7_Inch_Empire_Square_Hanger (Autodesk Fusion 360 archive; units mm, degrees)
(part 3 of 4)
  coincident L95 P256
  coincident L95 P257
  coincident L95 P258
  coincident L95 P259
  coincident L96 P260
  coincident L95 P261
  coincident L95 P262
  coincident L95 P263
  coincident L95 P264
  coincident L96 P265
  coincident L95 P266
  coincident L95 P267
  coincident L95 P268
  coincident L95 P269
  coincident L96 P270
  coincident L95 P271
  coincident L95 P272
  coincident L95 P273
  coincident L95 P274
  coincident L96 P275
  coincident L95 P276
  coincident L95 P277
  coincident L95 P278
  coincident L95 P279
  coincident L96 P280
  coincident L95 P281
  coincident L95 P282
  coincident L95 P283
  coincident P105 L96
  coincident P196 P284
  coincident P289 P290
  coincident P293 P295
  coincident P296 P298
  coincident P197 P295
  coincident P301 P303
  coincident P304 P306
  coincident P309 P311
  coincident P312 P314
  coincident P317 P319
  coincident P320 P322
  coincident P198 P303
  coincident P199 P311
  coincident P200 P319
  coincident P325 P327
  coincident P328 P330
  coincident P333 P335
  coincident P336 P338
  coincident P341 P343
  coincident P344 P346
  coincident P349 P351
  coincident P352 P354
  coincident P357 P359
  coincident P360 P362
  coincident P201 P327
  coincident P202 P335
  coincident P203 P343
  coincident P204 P351
  coincident P205 P359
  coincident P364 P368
  coincident P369 P371
  coincident P363 P368
  coincident P373 P377
  coincident P378 P380
  coincident P372 P377
  coincident P382 P386
  coincident P387 P389
  coincident P381 P386
  coincident P391 P395
  coincident P396 P398
  coincident P390 P395
  coincident P400 P404
  coincident P405 P407
  coincident P399 P404
  coincident P206 P368
  coincident P207 P377
  coincident P208 P386
  coincident P209 P395
  coincident P210 P404
  coincident P410 P411
  coincident P413 P417
  coincident P408 P411
  coincident P411 P416
  coincident P420 P421
  coincident P423 P437
  coincident P418 P421
  coincident P421 P426
  coincident P428 P432
  coincident P433 P435
  coincident P428 P431
  coincident P428 P436
  coincident P439 P443
  coincident P444 P446
  coincident P439 P442
  coincident P439 P447
  coincident P449 P453
  coincident P454 P456
  coincident P449 P452
  coincident P449 P457
  coincident P460 P461
  coincident P463 P467
  coincident P458 P461
  coincident P461 P466
  coincident P470 P471
  coincident P473 P477
  coincident P468 P471
  coincident P471 P476
  coincident P480 P481
  coincident P483 P497
  coincident P478 P481
  coincident P481 P486
  coincident P488 P492
  coincident P493 P495
  coincident P488 P491
  coincident P488 P496
  coincident P500 P501
  coincident P503 P517
  coincident P498 P501
  coincident P501 P506
  coincident P508 P512
  coincident P513 P515
  coincident P508 P511
  coincident P508 P516
  coincident P520 P521
  coincident P523 P537
  coincident P518 P521
  coincident P521 P526
  coincident P528 P532
  coincident P533 P535
  coincident P528 P531
  coincident P528 P536
  coincident P540 P541
  coincident P543 P557
  coincident P538 P541
  coincident P541 P546
  coincident P548 P552
  coincident P553 P555
  coincident P548 P551
  coincident P548 P556
  coincident P560 P561
  coincident P563 P577
  coincident P558 P561
  coincident P561 P566
  coincident P568 P572
  coincident P573 P575
  coincident P568 P571
  coincident P568 P576
  coincident P580 P581
  coincident P583 P587
  coincident P578 P581
  coincident P581 P586
  coincident P590 P591
  coincident P593 P607
  coincident P588 P591
  coincident P591 P596
  coincident P598 P602
  coincident P603 P605
  coincident P598 P601
  coincident P598 P606
  coincident P610 P611
  coincident P613 P627
  coincident P608 P611
  coincident P611 P616
  coincident P618 P622
  coincident P623 P625
  coincident P618 P621
  coincident P618 P626
  coincident P630 P631
  coincident P633 P647
  coincident P628 P631
  coincident P631 P636
  coincident P638 P642
  coincident P643 P645
  coincident P638 P641
  coincident P638 P646
  coincident P650 P651
  coincident P653 P667
  coincident P648 P651
  coincident P651 P656
  coincident P658 P662
  coincident P663 P665
  coincident P658 P661
  coincident P658 P666
  coincident P670 P671
  coincident P673 P687
  coincident P668 P671
  coincident P671 P676
  coincident P678 P682
  coincident P683 P685
  coincident P678 P681
  coincident P678 P686
  coincident P690 P691
  coincident P693 P707
  coincident P688 P691
  coincident P691 P696
  coincident P698 P702
  coincident P703 P705
  coincident P698 P701
  coincident P698 P706
  coincident P710 P711
  coincident P713 P727
  coincident P708 P711
  coincident P711 P716
  coincident P718 P722
  coincident P723 P725
  coincident P718 P721
  coincident P718 P726
  coincident P730 P731
  coincident P733 P747
  coincident P728 P731
  coincident P731 P736
  coincident P738 P742
  coincident P743 P745
  coincident P738 P741
  coincident P738 P746
  coincident P750 P751
  coincident P753 P767
  coincident P748 P751
  coincident P751 P756
  coincident P758 P762
  coincident P763 P765
  coincident P758 P761
  coincident P758 P766
  coincident P211 P421
  coincident P212 P439
  coincident P213 P449
  coincident P214 P461
  coincident P216 P481
  coincident P217 P501
  coincident P221 P581
  coincident P215 P471
  coincident P218 P528
  coincident P219 P541
  coincident P222 P591
  coincident P223 P618
  coincident P224 P631
  coincident P226 P678
  coincident P227 P691
  coincident P228 P711
  coincident P229 P738
  coincident P231 P411
  coincident P220 P561
  coincident P225 P658
  coincident P230 P751
  coincident P232 P428
  coincident P233 P758
  coincident P234 P731
  coincident P235 P718
  coincident P236 P698
  coincident P237 P671
  coincident P238 P651
  coincident P240 P638
  coincident P241 P611
  coincident P239 P598
  coincident P242 P568
  coincident P243 P548
  coincident P244 P521
  coincident P246 P488
  coincident P771 P774
  coincident P775 P777
  coincident P771 P773
  coincident P769 P771
  coincident P771 P778
  coincident P247 P771
  coincident P782 P785
  coincident P786 P788
  coincident P782 P784
  coincident P780 P782
  coincident P782 P789
  coincident P248 P782
  coincident P793 P796
  coincident P797 P799
  coincident P793 P795
  coincident P791 P793
  coincident P793 P800
  coincident P249 P793
  coincident P245 P508
  coincident P804 P807
  coincident P808 P810
  coincident P804 P806
  coincident P802 P804
  coincident P804 P811
  coincident P250 P804
  coincident P815 P818
  coincident P819 P821
  coincident P815 P817
  coincident P813 P815
  coincident P815 P822
  coincident P826 P829
  coincident P830 P832
  coincident P826 P828
  coincident P824 P826
  coincident P826 P833
  coincident P837 P840
  coincident P841 P843
  coincident P837 P839
  coincident P835 P837
  coincident P837 P844
  coincident P848 P851
  coincident P852 P854
  coincident P848 P850
  coincident P846 P848
  coincident P848 P855
  coincident P859 P862
  coincident P863 P865
  coincident P859 P861
  coincident P857 P859
  coincident P859 P866
  coincident P251 P815
  coincident P252 P826
  coincident P253 P837
  coincident P254 P848
  coincident P255 P859
  coincident P875 P877
  coincident P868 P869
  coincident P875 P876
  coincident P874 P875
  coincident P875 P878
  coincident P867 P875
  coincident P887 P889
  coincident P880 P881
  coincident P887 P888
  coincident P886 P887
  coincident P887 P890
  coincident P879 P887
  coincident P899 P901
  coincident P892 P893
  coincident P899 P900
  coincident P898 P899
  coincident P899 P902
  coincident P891 P899
  coincident P911 P913
  coincident P904 P905
  coincident P911 P912
  coincident P910 P911
  coincident P911 P914
  coincident P903 P911
  coincident P923 P925
  coincident P916 P917
  coincident P923 P924
  coincident P922 P923
  coincident P923 P926
  coincident P915 P923
  coincident P935 P937
  coincident P928 P929
  coincident P935 P936
  coincident P934 P935
  coincident P935 P938
  coincident P927 P935
  coincident P947 P949
  coincident P940 P941
  coincident P947 P948
  coincident P946 P947
  coincident P947 P950
  coincident P939 P947
  coincident P959 P961
  coincident P952 P953
  coincident P959 P960
  coincident P958 P959
  coincident P959 P962
  coincident P951 P959
  coincident P971 P973
  coincident P964 P965
  coincident P971 P972
  coincident P970 P971
  coincident P971 P974
  coincident P963 P971
  coincident P256 P875
  coincident P257 P887
  coincident P258 P899
  coincident P259 P911
  coincident P260 P923
  coincident P261 P935
  coincident P262 P947
  coincident P263 P959
  coincident P264 P971
  coincident P977 P979
  coincident P980 P982
  coincident P265 P979
  coincident P983 P985
  coincident P987 P990
  coincident P266 P985
  coincident P991 P993
  coincident P995 P998
  coincident P267 P993
  coincident P999 P1001
  coincident P1003 P1006
  coincident P268 P1001
  coincident P1007 P1009
  coincident P1011 P1014
  coincident P269 P1009
  coincident P1015 P1017
  coincident P1019 P1022
  coincident P270 P1017
  coincident P1023 P1025
  coincident P1027 P1030
  coincident P1031 P1033
  coincident P1035 P1038
  coincident P1039 P1041
  coincident P1043 P1046
  coincident P1047 P1049
  coincident P1051 P1054
  coincident P1055 P1057
  coincident P1059 P1062
  coincident P1063 P1065
  coincident P1067 P1070
  coincident P1071 P1073
  coincident P1075 P1078
  coincident P1079 P1081
  coincident P1083 P1086
  coincident P1087 P1089
  coincident P1091 P1094
  coincident P1095 P1097
  coincident P1099 P1102
  coincident P1103 P1105
  coincident P1107 P1110
  coincident P1111 P1113
  coincident P1115 P1118
  coincident P1119 P1121
  coincident P1123 P1126
  coincident P271 P1025
  coincident P272 P1033
  coincident P273 P1041
  coincident P274 P1049
  coincident P275 P1057
  coincident P276 P1065
  coincident P277 P1073
  coincident P278 P1081
  coincident P279 P1089
  coincident P280 P1097
  coincident P281 P1105
  coincident P282 P1113
  coincident P283 P1121
  dimension "d288" = 2.54
  dimension "d289" = 5.08
  dimension "d540" diameter = 0.635
  dimension "d544" distance P15 P289 = 0.635
  dimension "d545" diameter = 0.635
  dimension "d546" distance P110 P296 = 0.635
  dimension "d547" diameter = 0.635
  dimension "d548" distance P111 P304 = 0.635
  dimension "d549" diameter = 0.635
  dimension "d550" distance P112 P312 = 0.635
  dimension "d551" diameter = 0.635
  dimension "d552" distance P113 P320 = 0.635
  dimension "d553" diameter = 0.635
  dimension "d554" distance P114 P328 = 0.635
  dimension "d555" diameter = 0.635
  dimension "d556" distance P115 P336 = 0.635
  dimension "d557" diameter = 0.635
  dimension "d558" distance P116 P344 = 0.635
  dimension "d559" diameter = 0.635
  dimension "d560" distance P117 P352 = 0.635
  dimension "d561" diameter = 0.635
  dimension "d562" distance P118 P360 = 0.635
  dimension "d563" diameter = 0.635
  dimension "d564" distance P119 P369 = 0.635
  dimension "d565" diameter = 0.635
  dimension "d566" distance P120 P378 = 0.635
  dimension "d567" diameter = 0.635
  dimension "d568" distance P121 P387 = 0.635
  dimension "d569" diameter = 0.635
  dimension "d570" distance P122 P396 = 0.635
  dimension "d571" diameter = 0.635
  dimension "d572" distance P123 P405 = 0.635
  dimension "d573" diameter = 0.635
  dimension "d574" distance P144 P413 = 0.635
  dimension "d575" diameter = 0.635
  dimension "d576" distance P124 P423 = 0.635
  dimension "d577" diameter = 0.635
  dimension "d578" distance P145 P433 = 0.635
  dimension "d581" diameter = 0.635
  dimension "d582" distance P125 P444 = 0.635
  dimension "d585" diameter = 0.635
  dimension "d586" distance P126 P454 = 0.635
  dimension "d587" diameter = 0.635
  dimension "d588" distance P127 P463 = 0.635
  dimension "d591" diameter = 0.635
  dimension "d592" distance P128 P473 = 0.635
  dimension "d595" diameter = 0.635
  dimension "d596" distance P129 P483 = 0.635
  dimension "d597" diameter = 0.635
  dimension "d598" distance P159 P493 = 0.635
  dimension "d599" diameter = 0.635
  dimension "d600" distance P130 P503 = 0.635
  dimension "d601" diameter = 0.635
  dimension "d602" distance P158 P513 = 0.635
  dimension "d603" diameter = 0.635
  dimension "d604" distance P157 P523 = 0.635
  dimension "d605" diameter = 0.635
  dimension "d606" distance P131 P533 = 0.635
  dimension "d607" diameter = 0.635
  dimension "d608" distance P132 P543 = 0.635
  dimension "d609" diameter = 0.635
  dimension "d610" distance P156 P553 = 0.635
  dimension "d611" diameter = 0.635
  dimension "d612" distance P133 P563 = 0.635
  dimension "d613" diameter = 0.635
  dimension "d614" distance P155 P573 = 0.635
  dimension "d615" diameter = 0.635
  dimension "d616" distance P136 P583 = 0.635
  dimension "d619" diameter = 0.635
  dimension "d620" distance P134 P593 = 0.635
  dimension "d621" diameter = 0.635
  dimension "d622" distance P152 P603 = 0.635
  dimension "d623" diameter = 0.635
  dimension "d624" distance P154 P613 = 0.635
  dimension "d625" diameter = 0.635
  dimension "d626" distance P135 P623 = 0.635
  dimension "d627" diameter = 0.635
  dimension "d628" distance P137 P633 = 0.635
  dimension "d629" diameter = 0.635
  dimension "d630" distance P153 P643 = 0.635
  dimension "d631" diameter = 0.635
  dimension "d632" distance P151 P653 = 0.635
  dimension "d633" diameter = 0.635
  dimension "d634" distance P138 P663 = 0.635
  dimension "d635" diameter = 0.635
  dimension "d636" distance P150 P673 = 0.635
  dimension "d637" diameter = 0.635
  dimension "d638" distance P139 P683 = 0.635
  dimension "d639" diameter = 0.635
  dimension "d640" distance P140 P693 = 0.635
  dimension "d641" diameter = 0.635
  dimension "d642" distance P149 P703 = 0.635
  dimension "d643" diameter = 0.635
  dimension "d644" distance P141 P713 = 0.635
  dimension "d645" diameter = 0.635
  dimension "d646" distance P148 P723 = 0.635
  dimension "d647" diameter = 0.635
  dimension "d648" distance P146 P733 = 0.635
  dimension "d649" diameter = 0.635
  dimension "d650" distance P142 P743 = 0.635
  dimension "d651" diameter = 0.635
  dimension "d652" distance P143 P753 = 0.635
  dimension "d653" diameter = 0.635
  dimension "d654" distance P147 P763 = 0.635
  dimension "d655" diameter = 0.635
  dimension "d656" distance P160 P777 = 0.635
  dimension "d657" diameter = 0.635
  dimension "d658" distance P161 P788 = 0.635
  dimension "d659" diameter = 0.635
  dimension "d660" distance P162 P799 = 0.635
  dimension "d661" diameter = 0.635
  dimension "d662" distance P195 P810 = 0.635
  dimension "d663" diameter = 0.635
  dimension "d664" distance P163 P821 = 0.635
  dimension "d665" diameter = 0.635
  dimension "d666" distance P164 P832 = 0.635
  dimension "d667" diameter = 0.635
  dimension "d668" distance P165 P843 = 0.635
  dimension "d669" diameter = 0.635
  dimension "d670" distance P166 P854 = 0.635
  dimension "d671" diameter = 0.635
  dimension "d673" diameter = 0.635
  dimension "d675" diameter = 0.635
  dimension "d677" diameter = 0.635
  dimension "d679" diameter = 0.635
  dimension "d681" diameter = 0.635
  dimension "d683" diameter = 0.635
  dimension "d685" diameter = 0.635
  dimension "d687" diameter = 0.635
  dimension "d689" diameter = 0.635
  dimension "d693" distance P167 P865 = 0.635
  dimension "d694" distance P168 P868 = 0.635
  dimension "d695" distance P169 P880 = 0.635
  dimension "d696" distance P170 P892 = 0.635
  dimension "d697" distance P171 P904 = 0.635
  dimension "d698" distance P173 P916 = 0.635
  dimension "d699" distance P172 P928 = 0.635
  dimension "d700" distance P174 P940 = 0.635
  dimension "d701" distance P175 P952 = 0.635
  dimension "d702" distance P176 P964 = 0.635
  dimension "d703" diameter = 0.635
  dimension "d705" distance P177 P980 = 0.635
  dimension "d709" diameter = 0.635
  dimension "d710" distance P178 P987 = 0.635
  dimension "d711" diameter = 0.635
  dimension "d712" distance P179 P995 = 0.635
  dimension "d713" diameter = 0.635
  dimension "d714" distance P180 P1003 = 0.635
  dimension "d715" diameter = 0.635
  dimension "d716" distance P181 P1011 = 0.635
  dimension "d717" diameter = 0.635
  dimension "d718" distance P182 P1019 = 0.635
  dimension "d719" diameter = 0.635
  dimension "d720" distance P183 P1027 = 0.635
  dimension "d721" diameter = 0.635
  dimension "d722" distance P184 P1035 = 0.635
  dimension "d723" diameter = 0.635
  dimension "d724" distance P185 P1043 = 0.635
  dimension "d725" diameter = 0.635
  dimension "d726" distance P186 P1051 = 0.635
  dimension "d727" diameter = 0.635
  dimension "d728" distance P187 P1059 = 0.635
  dimension "d729" diameter = 0.635
  dimension "d730" distance P188 P1067 = 0.635
  dimension "d731" diameter = 0.635
  dimension "d732" distance P189 P1075 = 0.635
  dimension "d733" diameter = 0.635
  dimension "d734" distance P190 P1083 = 0.635
  dimension "d735" diameter = 0.635
  dimension "d736" distance P191 P1091 = 0.635
  dimension "d737" diameter = 0.635
  dimension "d738" distance P192 P1099 = 0.635
  dimension "d739" diameter = 0.635
  dimension "d740" distance P193 P1107 = 0.635
  dimension "d741" diameter = 0.635
  dimension "d742" distance P194 P1115 = 0.635
  dimension "d743" diameter = 0.635
  dimension "d744" distance P103 P1123 = 0.635
  dimension "d751" distance P1123 P1129 = 1.905
sketch "Front_Angular_Scale_Text" plane through (0, 0, 0) normal (0, 1, 0) x axis (1, 0, 0)
  line L1 (176.2125, 0) -> (0, 0)
  line L2 (0, 1.5875) -> (0, -176.2125)
  line L3 (0, -176.2125) -> (177.8, 1.5875)
  line L4 (-3.5921, -172.6204) -> (174.2079, 5.1796)
  line L5 (155.2888, -13.7395) -> (161.8891, -14.3234)
  line L6 (143.4449, -25.5834) -> (149.5418, -26.6707)
  line L7 (132.9775, -36.0508) -> (138.6294, -37.5831)
  line L8 (123.5209, -45.5074) -> (128.7709, -47.4416)
  line L9 (114.8064, -54.2219) -> (119.686, -56.5265)
  line L10 (106.6276, -62.4007) -> (111.1596, -65.0529)
  line L11 (98.8189, -70.2094) -> (103.019, -73.1935)
  line L12 (91.2406, -77.7877) -> (95.1186, -81.0939)
  line L13 (83.7683, -85.26) -> (87.3287, -88.8838)
  line L14 (76.2844, -92.7439) -> (79.5267, -96.6858)
  line L15 (68.6703, -100.358) -> (71.589, -104.6235)
  line L16 (60.7994, -108.2289) -> (63.3836, -112.8289)
  line L17 (52.5278, -116.5005) -> (54.7604, -121.4521)
  line L18 (43.6829, -125.3453) -> (45.5396, -130.6729)
  line L19 (34.0482, -134.9801) -> (35.4954, -140.7171)
  line L20 (23.3386, -145.6897) -> (24.3306, -151.8819)
  line L21 (11.1634, -157.8649) -> (11.6379, -164.5746)
  line L22 (151.9887, -13.4475) -> (155.2888, -13.7395)
  line L23 (140.3965, -25.0397) -> (143.4449, -25.5834)
  line L24 (130.1515, -35.2847) -> (132.9775, -36.0508)
  line L25 (120.8959, -44.5403) -> (123.5209, -45.5074)
  line L26 (112.3666, -53.0696) -> (114.8064, -54.2219)
  line L27 (104.3616, -61.0746) -> (106.6276, -62.4007)
  line L28 (96.7188, -68.7174) -> (98.8189, -70.2094)
  line L29 (89.3016, -76.1346) -> (91.2406, -77.7877)
  line L30 (81.9881, -83.4481) -> (83.7683, -85.26)
  line L31 (74.6632, -90.773) -> (76.2844, -92.7439)
  line L32 (67.211, -98.2252) -> (68.6703, -100.358)
  line L33 (59.5073, -105.9289) -> (60.7994, -108.2289)
  line L34 (51.4115, -114.0247) -> (52.5278, -116.5005)
  line L35 (42.7546, -122.6816) -> (43.6829, -125.3453)
  line L36 (33.3246, -132.1116) -> (34.0482, -134.9801)
  line L37 (22.8427, -142.5935) -> (23.3386, -145.6897)
  line L38 (10.9262, -154.51) -> (11.1634, -157.8649)
  line L39 (11.5708, -153.8654) -> (10.2816, -155.1546)
  line L40 (23.3041, -142.1321) -> (22.3812, -143.0549)
  line L41 (33.8532, -131.5829) -> (32.796, -132.6402)
  line L42 (43.7412, -121.695) -> (41.768, -123.6682)
  line L43 (52.5351, -112.9011) -> (50.2878, -115.1484)
  line L44 (60.7398, -104.6964) -> (58.2748, -107.1613)
  line L45 (69.0885, -96.3477) -> (65.3334, -100.1028)
  line L46 (76.888, -88.5482) -> (72.4384, -92.9978)
  line L47 (84.2675, -81.1687) -> (79.7087, -85.7275)
  line L48 (91.8124, -73.6238) -> (86.7908, -78.6454)
  line L49 (98.2574, -67.1788) -> (95.1802, -70.256)
  line L50 (106.2156, -59.2205) -> (102.5075, -62.9287)
  line L51 (113.766, -51.6702) -> (110.9671, -54.469)
  line L52 (122.4821, -42.9541) -> (119.3098, -46.1264)
  line L53 (132.1083, -33.3279) -> (128.1947, -37.2415)
  line L54 (142.7391, -22.6971) -> (138.0539, -27.3823)
  line L55 (154.2497, -11.1865) -> (149.7278, -15.7084)
  point P11 (155.2888, -13.7395)
  point P44 (155.2888, -13.7395)
  point P13 (143.4449, -25.5834)
  point P46 (143.4449, -25.5834)
  point P15 (132.9775, -36.0508)
  point P48 (132.9775, -36.0508)
  point P17 (123.5209, -45.5074)
  point P50 (123.5209, -45.5074)
  point P19 (114.8064, -54.2219)
  point P52 (114.8064, -54.2219)
  point P21 (106.6276, -62.4007)
  point P54 (106.6276, -62.4007)
  point P23 (98.8189, -70.2094)
  point P56 (98.8189, -70.2094)
  point P25 (91.2406, -77.7877)
  point P58 (91.2406, -77.7877)
  point P27 (83.7683, -85.26)
  point P60 (83.7683, -85.26)
  point P29 (76.2844, -92.7439)
  point P62 (76.2844, -92.7439)
  point P31 (68.6703, -100.358)
  point P64 (68.6703, -100.358)
  point P33 (60.7994, -108.2289)
  point P66 (60.7994, -108.2289)
  point P35 (52.5278, -116.5005)
  point P68 (52.5278, -116.5005)
  point P37 (43.6829, -125.3453)
  point P70 (43.6829, -125.3453)
  point P39 (34.0482, -134.9801)
  point P72 (34.0482, -134.9801)
  point P41 (23.3386, -145.6897)
  point P74 (23.3386, -145.6897)
  point P43 (11.1634, -157.8649)
  point P76 (11.1634, -157.8649)
  point P77 (10.9262, -154.51)
  point P75 (22.8427, -142.5935)
  point P45 (151.9887, -13.4475)
  point P47 (140.3965, -25.0397)
  point P49 (130.1515, -35.2847)
  point P51 (120.8959, -44.5403)
  point P53 (112.3666, -53.0696)
  point P55 (104.3616, -61.0746)
  point P57 (96.7188, -68.7174)
  point P59 (89.3016, -76.1346)
  point P61 (81.9881, -83.4481)
  point P63 (74.6632, -90.773)
  point P65 (67.211, -98.2252)
  point P67 (59.5073, -105.9289)
  point P69 (51.4115, -114.0247)
  point P71 (42.7546, -122.6816)
  point P73 (33.3246, -132.1116)
  coincident P11 P44
  parallel L5 L22
  coincident P13 P46
  parallel L6 L23
  coincident P15 P48
  parallel L7 L24
  coincident P17 P50
  parallel L8 L25
  coincident P19 P52
  parallel L9 L26
  coincident P21 P54
  parallel L10 L27
  coincident P23 P56
  parallel L11 L28
  coincident P25 P58
  parallel L12 L29
  coincident P27 P60
  coincident P29 P62
  parallel L14 L31
  coincident P31 P64
  parallel L15 L32
  coincident P33 P66
  parallel L16 L33
  coincident P35 P68
  parallel L17 L34
  coincident P37 P70
  parallel L18 L35
  coincident P39 P72
  parallel L19 L36
  coincident P41 P74
  parallel L20 L37
  coincident P43 P76
  parallel L21 L38
  midpoint P77 L39
  parallel L4 L39
  midpoint P75 L40
  parallel L4 L40
  midpoint P45 L55
  midpoint P47 L54
  midpoint P49 L53
  midpoint P51 L52
  midpoint P53 L51
  midpoint P55 L50
  midpoint P57 L49
  midpoint P59 L48
  midpoint P61 L47
  midpoint P63 L46
  midpoint P65 L45
  midpoint P67 L44
  midpoint P69 L43
  midpoint P71 L42
  midpoint P73 L41
  collinear L39 L40
  collinear L40 L41
  collinear L41 L42
  collinear L42 L43
  collinear L43 L44
  collinear L44 L45
  collinear L45 L46
  collinear L46 L47
  collinear L47 L48
  parallel L13 L30
  collinear L48 L49
  collinear L49 L50
  collinear L50 L51
  collinear L51 L52
  collinear L52 L53
  collinear L53 L54
  collinear L54 L55
  dimension "d929" distance L4 L55 = 2.54
  dimension "d930" Text1-Height = 3.175
  dimension "d931" Text2-Height = 3.175
  dimension "d932" Text3-Height = 3.175
  dimension "d933" Text4-Height = 3.175
  dimension "d934" Text5-Height = 3.175
  dimension "d935" Text6-Height = 3.175
  dimension "d936" Text7-Height = 3.175
  dimension "d937" Text8-Height = 3.175
  dimension "d938" Text9-Height = 3.175
sketch "Back_Angular_Text" plane through (0, 0, 0) normal (0, 1, 0) x axis (1, 0, 0)
  line L1 (89.3016, -76.1346) -> (91.2406, -77.7877)
  line L2 (23.304, -142.1321) -> (22.3813, -143.0549)
  line L3 (91.8124, -73.6238) -> (86.7908, -78.6454)
  line L4 (10.9262, -154.51) -> (11.1634, -157.8649)
  line L5 (52.5278, -116.5005) -> (54.7604, -121.4521)
  line L6 (33.8532, -131.583) -> (32.796, -132.6402)
  line L7 (11.5708, -153.8654) -> (10.2816, -155.1546)
  line L8 (34.0482, -134.9801) -> (35.4954, -140.7171)
  line L9 (42.7546, -122.6816) -> (43.6829, -125.3453)
  line L10 (22.8427, -142.5935) -> (23.3386, -145.6897)
  line L11 (33.3246, -132.1116) -> (34.0482, -134.9801)
  line L12 (11.1634, -157.8649) -> (11.6379, -164.5746)
  line L13 (106.2156, -59.2206) -> (102.5075, -62.9286)
  line L14 (76.8879, -88.5483) -> (72.4385, -92.9977)
  line L15 (98.8189, -70.2094) -> (103.019, -73.1935)
  line L16 (96.7188, -68.7174) -> (98.8189, -70.2094)
  line L17 (81.9881, -83.4481) -> (83.7683, -85.26)
  line L18 (112.3666, -53.0696) -> (114.8064, -54.2219)
  line L19 (132.1083, -33.3279) -> (128.1948, -37.2414)
  line L20 (120.8959, -44.5403) -> (123.5209, -45.5074)
  line L21 (155.2888, -13.7395) -> (161.8891, -14.3234)
  line L22 (104.3616, -61.0746) -> (106.6276, -62.4007)
  line L23 (123.5209, -45.5074) -> (128.7709, -47.4416)
  line L24 (60.7994, -108.2289) -> (63.3836, -112.8289)
  line L25 (91.2406, -77.7877) -> (95.1186, -81.0939)
  line L26 (83.7683, -85.26) -> (87.3287, -88.8838)
  line L27 (60.7398, -104.6964) -> (58.2749, -107.1613)
  line L28 (106.6276, -62.4007) -> (111.1596, -65.0529)
  line L29 (114.8064, -54.2219) -> (119.686, -56.5265)
  line L30 (113.766, -51.6702) -> (110.9672, -54.469)
  line L31 (84.2674, -81.1687) -> (79.7088, -85.7274)
  line L32 (122.4821, -42.9541) -> (119.3098, -46.1264)
  line L33 (43.7412, -121.695) -> (41.768, -123.6682)
  line L34 (142.7391, -22.6971) -> (138.054, -27.3822)
  line L35 (98.2574, -67.1788) -> (95.1802, -70.2559)
  line L36 (51.4115, -114.0247) -> (52.5278, -116.5005)
  line L37 (68.6703, -100.358) -> (71.589, -104.6235)
  line L38 (23.3386, -145.6897) -> (24.3306, -151.8819)
  line L39 (43.6829, -125.3453) -> (45.5396, -130.6729)
  line L40 (76.2844, -92.7439) -> (79.5267, -96.6858)
  line L41 (143.4449, -25.5834) -> (149.5418, -26.6707)
  line L42 (59.5073, -105.9289) -> (60.7994, -108.2289)
  line L43 (130.1515, -35.2847) -> (132.9775, -36.0508)
  line L44 (67.211, -98.2252) -> (68.6703, -100.358)
  line L45 (132.9775, -36.0508) -> (138.6294, -37.5831)
  line L46 (74.6632, -90.773) -> (76.2844, -92.7439)
  line L47 (154.2496, -11.1866) -> (149.7278, -15.7084)
  line L48 (151.9887, -13.4475) -> (155.2888, -13.7395)
  line L49 (140.3965, -25.0397) -> (143.4449, -25.5834)
  line L50 (52.5351, -112.9011) -> (50.2878, -115.1484)
  line L51 (69.0885, -96.3477) -> (65.3335, -100.1027)
  line L52 (0, -176.2125) -> (177.8, 1.5875)
  line L53 (-3.5921, -172.6204) -> (174.2079, 5.1796)
  line L54 (176.2125, 0) -> (0, 0)
  line L55 (0, 1.5875) -> (0, -176.2125)
  point P16 (155.2888, -13.7395)
  point P72 (155.2888, -13.7395)
  point P27 (143.4449, -25.5834)
  point P98 (143.4449, -25.5834)
  point P24 (132.9775, -36.0508)
  point P100 (132.9775, -36.0508)
  point P28 (123.5209, -45.5074)
  point P53 (123.5209, -45.5074)
  point P17 (114.8064, -54.2219)
  point P83 (114.8064, -54.2219)
  point P18 (106.6276, -62.4007)
  point P85 (106.6276, -62.4007)
  point P11 (98.8189, -70.2094)
  point P19 (98.8189, -70.2094)
  point P20 (91.2406, -77.7877)
  point P80 (91.2406, -77.7877)
  point P14 (83.7683, -85.26)
  point P34 (83.7683, -85.26)
  point P22 (76.2844, -92.7439)
  point P71 (76.2844, -92.7439)
  point P37 (68.6703, -100.358)
  point P62 (68.6703, -100.358)
  point P39 (60.7994, -108.2289)
  point P60 (60.7994, -108.2289)
  point P41 (52.5278, -116.5005)
  point P68 (52.5278, -116.5005)
  point P9 (43.6829, -125.3453)
  point P46 (43.6829, -125.3453)
  point P8 (34.0482, -134.9801)
  point P45 (34.0482, -134.9801)
  point P43 (23.3386, -145.6897)
  point P54 (23.3386, -145.6897)
  point P49 (11.1634, -157.8649)
  point P58 (11.1634, -157.8649)
  point P57 (10.9262, -154.51)
  point P59 (22.8427, -142.5935)
  point P73 (151.9887, -13.4475)
  point P99 (140.3965, -25.0397)
  point P96 (130.1515, -35.2847)
  point P52 (120.8959, -44.5403)
  point P84 (112.3666, -53.0696)
  point P88 (104.3616, -61.0746)
  point P13 (96.7188, -68.7174)
  point P81 (89.3016, -76.1346)
  point P15 (81.9881, -83.4481)
  point P70 (74.6632, -90.773)
  point P63 (67.211, -98.2252)
  point P61 (59.5073, -105.9289)
  point P69 (51.4115, -114.0247)
  point P10 (42.7546, -122.6816)
  point P12 (33.3246, -132.1116)
  point P21 (161.8891, -14.3234)
  point P113 (161.8891, -14.3234)
  point P25 (149.5418, -26.6707)
  point P114 (149.5418, -26.6707)
  point P23 (138.6294, -37.5831)
  point P115 (138.6294, -37.5831)
  point P26 (128.7709, -47.4416)
  point P116 (128.7709, -47.4416)
  point P29 (119.686, -56.5265)
  point P117 (119.686, -56.5265)
  point P30 (111.1596, -65.0529)
  point P118 (111.1596, -65.0529)
  point P31 (103.019, -73.1935)
  point P119 (103.019, -73.1935)
  point P32 (95.1186, -81.0939)
  point P120 (95.1186, -81.0939)
  point P33 (87.3287, -88.8838)
  point P121 (87.3287, -88.8838)
  point P35 (79.5267, -96.6858)
  point P122 (79.5267, -96.6858)
  point P36 (71.589, -104.6235)
  point P123 (71.589, -104.6235)
  point P38 (63.3836, -112.8289)
  point P124 (63.3836, -112.8289)
  point P40 (54.7604, -121.4521)
  point P125 (54.7604, -121.4521)
  point P42 (45.5396, -130.6729)
  point P126 (45.5396, -130.6729)
  point P44 (35.4954, -140.7171)
  point P127 (35.4954, -140.7171)
  point P48 (24.3306, -151.8819)
  point P128 (24.3306, -151.8819)
  point P47 (11.6379, -164.5746)
  point P129 (11.6379, -164.5746)
  point P130 (11.1634, -157.8649)
  point P131 (23.3386, -145.6897)
  point P132 (34.0482, -134.9801)
  point P133 (43.6829, -125.3453)
  point P134 (52.5278, -116.5005)
  point P135 (60.7994, -108.2289)
  point P136 (68.6703, -100.358)
  point P137 (76.2844, -92.7439)
  point P138 (83.7683, -85.26)
  point P139 (91.2406, -77.7877)
  point P140 (98.8189, -70.2094)
  point P141 (106.6276, -62.4007)
  point P142 (114.8064, -54.2219)
  point P143 (123.5209, -45.5074)
  point P144 (132.9775, -36.0508)
  point P145 (143.4449, -25.5834)
  point P146 (155.2888, -13.7395)
  coincident P16 P72
  parallel L21 L48
  coincident P27 P98
  parallel L41 L49
  coincident P24 P100
  parallel L43 L45
  coincident P28 P53
  parallel L20 L23
  coincident P17 P83
  parallel L18 L29
  coincident P18 P85
  parallel L22 L28
  coincident P11 P19
  parallel L15 L16
  coincident P20 P80
  parallel L1 L25
  coincident P14 P34
  coincident P22 P71
  parallel L40 L46
  coincident P37 P62
  parallel L37 L44
  coincident P39 P60
  parallel L24 L42
  coincident P41 P68
  parallel L5 L36
  coincident P9 P46
  parallel L9 L39
  coincident P8 P45
  parallel L8 L11
  coincident P43 P54
  parallel L10 L38
  coincident P49 P58
  parallel L4 L12
  midpoint P57 L7
  midpoint P59 L2
  midpoint P73 L47
  midpoint P99 L34
  midpoint P96 L19
  midpoint P52 L32
  midpoint P84 L30
  midpoint P88 L13
  midpoint P13 L35
  midpoint P81 L3
  midpoint P15 L31
  midpoint P70 L14
  midpoint P63 L51
  midpoint P61 L27
  midpoint P69 L50
  midpoint P10 L33
  midpoint P12 L6
  collinear L2 L7
  collinear L2 L6
  collinear L6 L33
  collinear L33 L50
  collinear L27 L50
  collinear L27 L51
  collinear L14 L51
  collinear L14 L31
  collinear L3 L31
  parallel L17 L26
  collinear L3 L35
  collinear L13 L35
  collinear L13 L30
  collinear L30 L32
  collinear L19 L32
  collinear L19 L34
  collinear L34 L47
  coincident P21 L52
  coincident P21 P113
  coincident P25 P114
  coincident P23 P115
  coincident P26 P116
  coincident P29 P117
  coincident P30 P118
  coincident P31 P119
  coincident P32 P120
  coincident P33 P121
  coincident P35 P122
  coincident P36 P123
  coincident P38 P124
  coincident P40 P125
  coincident P42 P126
  coincident P44 P127
  coincident P48 P128
  coincident P47 P129
  coincident P49 P130
  coincident P43 P131
  coincident P45 P132
  coincident P46 P133
  coincident P68 P134
  coincident P60 P135
  coincident P37 P136
  coincident P22 P137
  coincident P14 P138
  coincident P20 P139
  coincident P19 P140
  coincident P85 P141
  coincident P83 P142
  coincident P53 P143
  coincident P24 P144
  coincident P27 P145
  coincident P16 P146
  parallel L47 L53
  dimension "d949" distance L47 L53 = 2.54
  dimension "d939" Text1-Height = 3.175
  dimension "d940" Text2-Height = 3.175
  dimension "d941" Text3-Height = 3.175
  dimension "d942" Text4-Height = 3.175
  dimension "d943" Text5-Height = 3.175
  dimension "d944" Text6-Height = 3.175
  dimension "d945" Text7-Height = 3.175
  dimension "d946" Text8-Height = 3.175
  dimension "d947" Text9-Height = 3.175
sketch "Angular_Common_Rafter" plane through (0, 0, 0) normal (0, 1, 0) x axis (1, 0, 0)
  line L1 (131.0388, -4.7625) -> (38.1, -97.7013)
  line L2 (0, 1.5875) -> (0, -176.2125)
  line L3 (177.8, 1.5875) -> (0, 1.5875)
  line L4 (0, -176.2125) -> (177.8, 1.5875)
  line L5 (38.1, -97.7013) -> (38.1, -88.7211)
  line L6 (122.0586, -4.7625) -> (131.0388, -4.7625)
  line L7 (38.1, -88.7211) -> (122.0586, -4.7625)
  line L8 (124.8761, -10.9252) -> (0, 0)
  line L9 (116.3338, -19.4676) -> (0, 0)
  line L10 (108.6995, -27.1018) -> (0, 0)
  line L11 (101.7547, -34.0466) -> (0, 0)
  line L12 (96.0261, -39.7753) -> (0, 0)
  line L13 (90.6199, -45.1814) -> (0, 0)
  line L14 (85.7774, -50.0239) -> (0, 0)
  line L15 (81.407, -54.3944) -> (0, 0)
  line L16 (77.4435, -58.3579) -> (0, 0)
  line L17 (74.1399, -61.6615) -> (0, 0)
  line L18 (70.8653, -64.9361) -> (0, 0)
  line L19 (67.9007, -67.9007) -> (0, 0)
  line L20 (65.1735, -70.6278) -> (0, 0)
  line L21 (62.676, -73.1253) -> (0, 0)
  line L22 (60.4044, -75.397) -> (0, 0)
  line L23 (58.237, -77.5644) -> (0, 0)
  line L24 (56.1722, -79.6292) -> (0, 0)
  line L25 (176.2125, 0) -> (0, 0)
  line L26 (54.3328, -81.4686) -> (0, 0)
  line L27 (52.5986, -83.2028) -> (0, 0)
  line L28 (50.9711, -84.8302) -> (0, 0)
  line L29 (49.3252, -86.4762) -> (0, 0)
  line L30 (47.9164, -87.8849) -> (0, 0)
  line L31 (46.6219, -89.1795) -> (0, 0)
  line L32 (45.3131, -90.4882) -> (0, 0)
  line L33 (39.0785, -96.7228) -> (0, 0)
  line L34 (131.4547, -11.8195) -> (124.2158, -11.1862)
  line L35 (124.2712, -10.5536) -> (131.51, -11.1869)
  line L36 (131.4823, -11.5032) -> (124.2435, -10.8699)
  line L37 (132.8349, -6.5586) -> (39.8961, -99.4974)
  line L38 (134.6309, -8.3546) -> (41.6921, -101.2934)
  line L39 (131.4823, -11.5032) -> (124.8761, -10.9252)
  line L40 (122.4881, -20.4975) -> (116.3338, -19.4676)
  line L41 (114.45, -28.5356) -> (108.6995, -27.1018)
  line L42 (107.1378, -35.8478) -> (101.7547, -34.0466)
  line L43 (101.1061, -41.8795) -> (96.0261, -39.7753)
  line L44 (95.4139, -47.5716) -> (90.6199, -45.1814)
  line L45 (90.3153, -52.6703) -> (85.7774, -50.0239)
  line L46 (85.7136, -57.272) -> (81.407, -54.3944)
  line L47 (81.5404, -61.4451) -> (77.4435, -58.3579)
  line L48 (78.062, -64.9235) -> (74.1399, -61.6615)
  line L49 (74.6142, -68.3713) -> (70.8653, -64.9361)
  line L50 (71.4928, -71.4928) -> (67.9007, -67.9007)
  line L51 (68.6213, -74.3642) -> (65.1735, -70.6278)
  line L52 (65.9917, -76.9938) -> (62.676, -73.1253)
  line L53 (63.5999, -79.3857) -> (60.4044, -75.397)
  line L54 (61.3178, -81.6677) -> (58.237, -77.5644)
  line L55 (59.1438, -83.8417) -> (56.1722, -79.6292)
  line L56 (57.2071, -85.7784) -> (54.3328, -81.4686)
  line L57 (55.3812, -87.6044) -> (52.5986, -83.2028)
  line L58 (53.6676, -89.3179) -> (50.9711, -84.8302)
  line L59 (51.9346, -91.051) -> (49.3252, -86.4762)
  line L60 (50.4513, -92.5342) -> (47.9164, -87.8849)
  line L61 (49.0883, -93.8973) -> (46.6219, -89.1795)
  line L62 (47.7103, -95.2753) -> (45.3132, -90.4883)
  line L63 (122.4881, -20.4975) -> (115.7075, -19.3628)
  line L64 (122.4357, -20.8106) -> (115.6551, -19.6759)
  line L65 (115.7599, -19.0496) -> (122.5405, -20.1843)
  line L66 (114.45, -28.5356) -> (108.0834, -26.9482)
  line L67 (114.3732, -28.8437) -> (108.0066, -27.2563)
  line L68 (108.1602, -26.6401) -> (114.5268, -28.2275)
  line L69 (107.1378, -35.8478) -> (101.1525, -33.8452)
  line L70 (107.037, -36.1489) -> (101.0518, -34.1463)
  line L71 (101.2533, -33.5441) -> (107.2385, -35.5467)
  line L72 (101.1061, -41.8795) -> (95.4394, -39.5323)
  line L73 (100.9846, -42.1728) -> (95.3179, -39.8256)
  line L74 (95.5609, -39.239) -> (101.2276, -41.5862)
  line L75 (95.4139, -47.5716) -> (90.0516, -44.8981)
  line L76 (95.2723, -47.8558) -> (89.91, -45.1822)
  line L77 (90.1933, -44.6139) -> (95.5556, -47.2875)
  line L78 (90.3153, -52.6703) -> (85.2289, -49.704)
  line L79 (90.1553, -52.9446) -> (85.0689, -49.9783)
  line L80 (85.3888, -49.4298) -> (90.4752, -52.396)
  line L81 (85.7136, -57.272) -> (80.879, -54.0416)
  line L82 (85.5372, -57.536) -> (80.7026, -54.3056)
  line L83 (81.0554, -53.7776) -> (85.89, -57.008)
  line L84 (81.5404, -61.4451) -> (76.9364, -57.9757)
  line L85 (81.3494, -61.6987) -> (76.7453, -58.2293)
  line L86 (77.1274, -57.7221) -> (81.7315, -61.1916)
  line L87 (78.062, -64.9235) -> (73.6517, -61.2554)
  line L88 (77.859, -65.1676) -> (73.4486, -61.4995)
  line L89 (73.8547, -61.0113) -> (78.2651, -64.6794)
  line L90 (74.6142, -68.3713) -> (70.3971, -64.5071)
  line L91 (74.3997, -68.6054) -> (70.1826, -64.7412)
  line L92 (70.6116, -64.273) -> (74.8287, -68.1372)
  line L93 (71.4928, -71.4928) -> (67.4517, -67.4517)
  line L94 (71.2683, -71.7173) -> (67.2272, -67.6762)
  line L95 (67.6762, -67.2272) -> (71.7173, -71.2683)
  line L96 (68.6213, -74.3642) -> (64.7429, -70.1612)
  line L97 (68.388, -74.5795) -> (64.5095, -70.3765)
  line L98 (64.9762, -69.9459) -> (68.8547, -74.1489)
  line L99 (65.9917, -76.9938) -> (62.2628, -72.6432)
  line L100 (65.7506, -77.2005) -> (62.0217, -72.8498)
  line L101 (62.5038, -72.4366) -> (66.2328, -76.7872)
  line L102 (63.5999, -79.3857) -> (60.0073, -74.9014)
  line L103 (63.3521, -79.5842) -> (59.7596, -75.0999)
  line L104 (60.2551, -74.7029) -> (63.8477, -79.1871)
  line L105 (61.3178, -81.6677) -> (57.8557, -77.0566)
  line L106 (61.0639, -81.8583) -> (57.6018, -77.2472)
  line L107 (58.1096, -76.8659) -> (61.5717, -81.4771)
  line L108 (59.1438, -83.8417) -> (55.8062, -79.1103)
  line L109 (58.8844, -84.0247) -> (55.5467, -79.2933)
  line L110 (56.0656, -78.9273) -> (59.4033, -83.6587)
  line L111 (57.2071, -85.7784) -> (53.9805, -80.9403)
  line L112 (56.943, -85.9546) -> (53.7163, -81.1164)
  line L113 (54.2446, -80.7641) -> (57.4713, -85.6023)
  line L114 (55.3812, -87.6044) -> (52.2593, -82.666)
  line L115 (55.1128, -87.774) -> (51.9909, -82.8357)
  line L116 (52.5277, -82.4964) -> (55.6496, -87.4347)
  line L117 (53.6676, -89.3179) -> (50.6441, -84.2859)
  line L118 (53.3955, -89.4815) -> (50.3719, -84.4494)
  line L119 (50.9162, -84.1224) -> (53.9398, -89.1544)
  line L120 (51.9346, -91.051) -> (49.0105, -85.9246)
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  point P1 (0, 0)
  point P16 (0, 0)
  point P17 (124.8761, -10.9252)
  point P18 (0, 0)
  point P19 (116.3338, -19.4676)
  point P20 (0, 0)
  point P21 (108.6995, -27.1018)
  point P22 (0, 0)
  point P23 (101.7547, -34.0466)
  point P24 (0, 0)
  point P25 (96.0261, -39.7753)
  point P26 (0, 0)
  point P27 (90.6199, -45.1814)
  point P28 (85.7774, -50.0239)
  point P29 (0, 0)
  point P30 (81.407, -54.3944)
  point P31 (77.4435, -58.3579)
  point P32 (74.1399, -61.6615)
  point P33 (70.8653, -64.9361)
  point P34 (67.9007, -67.9007)
  point P35 (0, 0)
  point P36 (65.1735, -70.6278)
  point P37 (0, 0)
  point P38 (62.676, -73.1253)
  point P39 (0, 0)
  point P40 (60.4044, -75.397)
  point P41 (0, 0)
  point P42 (58.237, -77.5644)
  point P43 (56.1722, -79.6292)
  point P44 (176.2125, 0)
  point P45 (54.3328, -81.4686)
  point P46 (52.5986, -83.2028)
  point P47 (50.9711, -84.8302)
  point P48 (49.3252, -86.4762)
  point P49 (47.9164, -87.8849)
  point P50 (46.6219, -89.1795)
  point P51 (45.3131, -90.4882)
  point P52 (39.0785, -96.7228)
  point P59 (124.8761, -10.9252)
  point P64 (131.4823, -11.5032)
  point P65 (122.4881, -20.4975)
  point P66 (114.45, -28.5356)
  point P67 (107.1378, -35.8478)
  point P68 (101.1061, -41.8795)
  point P69 (95.4139, -47.5716)
  point P70 (90.3153, -52.6703)
  point P71 (85.7136, -57.272)
  point P72 (81.5404, -61.4451)
  point P73 (78.062, -64.9235)
  point P74 (74.6142, -68.3713)
  point P75 (71.4928, -71.4928)
  point P76 (68.6213, -74.3642)
  point P77 (65.9917, -76.9938)
  point P78 (63.5999, -79.3857)
  point P79 (61.3178, -81.6677)
  point P80 (59.1438, -83.8417)
  point P81 (57.2071, -85.7784)
  point P82 (55.3812, -87.6044)
  point P83 (53.6676, -89.3179)
  point P84 (51.9346, -91.051)
  point P85 (50.4513, -92.5342)
  point P86 (49.0883, -93.8973)
  point P89 (47.7103, -95.2753)
  point P58 (131.4823, -11.5032)
  point P96 (116.3338, -19.4676)
  point P103 (108.6995, -27.1018)
  point P110 (101.7547, -34.0466)
  point P117 (96.0261, -39.7753)
  point P124 (90.6199, -45.1814)
  point P131 (85.7774, -50.0239)
  point P138 (81.407, -54.3944)
  point P145 (77.4435, -58.3579)
  point P152 (74.1399, -61.6615)
  point P159 (70.8653, -64.9361)
  point P166 (67.9007, -67.9007)
  point P173 (65.1735, -70.6278)
  point P180 (62.676, -73.1253)
  point P187 (60.4044, -75.397)
  point P194 (58.237, -77.5644)
  point P201 (56.1722, -79.6292)
  point P208 (54.3328, -81.4686)
  point P215 (52.5986, -83.2028)
  point P222 (50.9711, -84.8302)
  point P90 (122.4881, -20.4975)
  point P97 (114.45, -28.5356)
  point P104 (107.1378, -35.8478)
  point P111 (101.1061, -41.8795)
  point P118 (95.4139, -47.5716)
  point P125 (90.3153, -52.6703)
  point P132 (85.7136, -57.272)
  point P139 (81.5404, -61.4451)
  point P146 (78.062, -64.9235)
  point P153 (74.6142, -68.3713)
  point P160 (71.4928, -71.4928)
  point P167 (68.6213, -74.3642)
  point P174 (65.9917, -76.9938)
  point P181 (63.5999, -79.3857)
  point P188 (61.3178, -81.6677)
  point P195 (59.1438, -83.8417)
  point P202 (57.2071, -85.7784)
  point P209 (55.3812, -87.6044)
  point P216 (53.6676, -89.3179)
  point P229 (49.3252, -86.4762)
  point P223 (51.9346, -91.051)
  point P230 (50.4513, -92.5342)
  point P236 (47.9164, -87.8849)
  point P244 (49.0883, -93.8973)
  point P250 (46.6219, -89.1795)
  point P237 (47.7103, -95.2753)
  point P243 (45.3131, -90.4882)
  point P57 (124.2435, -10.8699)
  point P93 (115.7075, -19.3628)
  point P100 (108.0834, -26.9482)
  point P107 (101.1525, -33.8452)
  point P114 (95.4394, -39.5323)
  point P121 (90.0516, -44.8981)
  point P128 (85.2289, -49.704)
  point P135 (80.879, -54.0416)
  point P142 (76.9364, -57.9757)
  point P149 (73.6517, -61.2554)
  point P156 (70.3971, -64.5071)
  point P163 (67.4517, -67.4517)
  point P170 (64.7429, -70.1612)
  point P177 (62.2628, -72.6432)
  point P184 (60.0073, -74.9014)
  point P191 (57.8557, -77.0566)
  point P198 (55.8062, -79.1103)
  point P205 (53.9805, -80.9403)
  point P212 (52.2593, -82.666)
  point P219 (50.6441, -84.2859)
  point P226 (49.0105, -85.9246)
  point P233 (47.6124, -87.3274)
  point P240 (45.0288, -89.9204)
  point P247 (46.3277, -88.6167)
  coincident P1 P16
  coincident L1 P17
  coincident P1 P18
  coincident L1 P19
  coincident P1 P20
  coincident L1 P21
  coincident P1 P22
  coincident L1 P23
  coincident P1 P24
  coincident L1 P25
  coincident P1 P26
  coincident L1 P27
  coincident L1 P28
  coincident P1 P29
  coincident L1 P30
  coincident L1 P31
  coincident L1 P32
  coincident L1 P33
  coincident L1 P34
  coincident P1 P35
  coincident L1 P36
  coincident P1 P37
  coincident L1 P38
  coincident P1 P39
  coincident L1 P40
  coincident P1 P41
  coincident L1 P42
  coincident L1 P43
  coincident L4 P44
  horizontal L25
  coincident L1 P45
  coincident L1 P46
  coincident L1 P47
  coincident L1 P48
  coincident L1 P49
  coincident L1 P50
  coincident L1 P51
  coincident L1 P52
  parallel L34 L35
  coincident L36 P59
  coincident L38 P64
  coincident L38 P65
  coincident L38 P66
  coincident L38 P67
  coincident L38 P68
  coincident L38 P69
  collinear L8 L39
  collinear L9 L40
  collinear L10 L41
  collinear L11 L42
  collinear L12 L43
  collinear L13 L44
  coincident L38 P70
  coincident L38 P71
  coincident L38 P72
  coincident L38 P73
  coincident L38 P74
  coincident L38 P75
  coincident L38 P76
  coincident L38 P77
  coincident L38 P78
  coincident L38 P79
  coincident L38 P80
  coincident L38 P81
  coincident L38 P82
  coincident L38 P83
  coincident L38 P84
  coincident L38 P85
  coincident L38 P86
  coincident L38 P89
  collinear L32 L62
  collinear L31 L61
  collinear L30 L60
  collinear L29 L59
  collinear L28 L58
  collinear L27 L57
  collinear L26 L56
  collinear L24 L55
  collinear L23 L54
  collinear L22 L53
  collinear L21 L52
  collinear L20 L51
  collinear L19 L50
  collinear L18 L49
  collinear L17 L48
  collinear L16 L47
  collinear L15 L46
  collinear L14 L45
  coincident P17 P59
  coincident P58 P64
  parallel L64 L65
  coincident P96 L63
  parallel L67 L68
  coincident P103 L66
  parallel L70 L71
  coincident P110 L69
  parallel L73 L74
  coincident P117 L72
  parallel L76 L77
  coincident P124 L75
  parallel L79 L80
  coincident P131 L78
  parallel L82 L83
  coincident P138 L81
  parallel L85 L86
  coincident P145 L84
  parallel L88 L89
  coincident P152 L87
  parallel L91 L92
  coincident P159 L90
  parallel L94 L95
  coincident P166 L93
  parallel L97 L98
  coincident P173 L96
  parallel L100 L101
  coincident P180 L99
  parallel L103 L104
  coincident P187 L102
  parallel L106 L107
  coincident P194 L105
  parallel L109 L110
  coincident P201 L108
  parallel L112 L113
  coincident P208 L111
  parallel L115 L116
  coincident P215 L114
  parallel L118 L119
  coincident P222 L117
  coincident P19 P96
  coincident P65 P90
  coincident P21 P103
  coincident P66 P97
  coincident P23 P110
  coincident P67 P104
  coincident P25 P117
  coincident P68 P111
  coincident P27 P124
  coincident P69 P118
  coincident P28 P131
  coincident P70 P125
  coincident P30 P138
  coincident P71 P132
  coincident P31 P145
  coincident P72 P139
  coincident P32 P152
  coincident P73 P146
  coincident P33 P159
  coincident P74 P153
  coincident P34 P166
  coincident P75 P160
  coincident P36 P173
  coincident P76 P167
  coincident P38 P180
  coincident P77 P174
  coincident P40 P187
  coincident P78 P181
  coincident P42 P194
  coincident P79 P188
  coincident P43 P201
  coincident P80 P195
  coincident P45 P208
  coincident P81 P202
  coincident P46 P215
  coincident P82 P209
  coincident P47 P222
  coincident P83 P216
  coincident P229 L120
  coincident P84 P223
  coincident P48 P229
  coincident P85 P230
  coincident P49 P236
  coincident P86 P244
  coincident P50 P250
  coincident P89 P237
  coincident P51 P243
  dimension "d539" angle L3 L8 = 5
  dimension "d752" angle L3 L9 = 9.5
  dimension "d753" angle L3 L10 = 14
  dimension "d754" angle L3 L11 = 18.5
  dimension "d755" angle L3 L12 = 22.5
  dimension "d756" angle L3 L13 = 26.5
  dimension "d757" angle L3 L14 = 30.25
  dimension "d758" angle L3 L15 = 33.75
  dimension "d759" angle L3 L16 = 37
  dimension "d760" angle L3 L17 = 39.75
  dimension "d761" angle L3 L18 = 42.5
  dimension "d763" angle L3 L19 = 45
  dimension "d764" angle L3 L20 = 47.3
  dimension "d765" angle L3 L21 = 49.4
  dimension "d766" angle L3 L22 = 51.3
  dimension "d767" angle L3 L23 = 53.1
  dimension "d768" angle L3 L24 = 54.8
  dimension "d769" angle L3 L26 = 56.3
  dimension "d770" angle L3 L27 = 57.7
  dimension "d771" angle L3 L28 = 59
  dimension "d772" angle L3 L29 = 60.3
  dimension "d773" angle L3 L30 = 61.4
  dimension "d774" angle L3 L31 = 62.4
  dimension "d775" angle L3 L32 = 63.4
  dimension "d776" angle L3 L33 = 68
  dimension "d800" diameter = 0.635
  dimension "d801" distance P57 P59 = 0.635
  dimension "d802" = 2.54
  dimension "d803" = 5.08
  dimension "d804" diameter = 0.635
  dimension "d805" distance P93 P96 = 0.635
  dimension "d806" diameter = 0.635
  dimension "d807" distance P100 P103 = 0.635
  dimension "d808" diameter = 0.635
  dimension "d809" distance P107 P110 = 0.635
  dimension "d810" diameter = 0.635
  dimension "d811" distance P114 P117 = 0.635
  dimension "d812" diameter = 0.635
  dimension "d813" distance P121 P124 = 0.635
  dimension "d814" diameter = 0.635
  dimension "d815" distance P128 P131 = 0.635
  dimension "d816" diameter = 0.635
  dimension "d817" distance P135 P138 = 0.635
  dimension "d818" diameter = 0.635
  dimension "d819" distance P142 P145 = 0.635
  dimension "d820" diameter = 0.635
  dimension "d821" distance P149 P152 = 0.635
  dimension "d822" diameter = 0.635
  dimension "d823" distance P156 P159 = 0.635
  dimension "d824" diameter = 0.635
  dimension "d825" distance P163 P166 = 0.635
  dimension "d826" diameter = 0.635
  dimension "d827" distance P170 P173 = 0.635
  dimension "d828" diameter = 0.635
  dimension "d829" distance P177 P180 = 0.635
  dimension "d830" diameter = 0.635
  dimension "d831" distance P184 P187 = 0.635
  dimension "d832" diameter = 0.635
  dimension "d833" distance P191 P194 = 0.635
  dimension "d834" diameter = 0.635
  dimension "d835" distance P198 P201 = 0.635
  dimension "d836" diameter = 0.635
  dimension "d837" distance P205 P208 = 0.635
  dimension "d838" diameter = 0.635
  dimension "d839" distance P212 P215 = 0.635
  dimension "d840" diameter = 0.635
  dimension "d841" distance P219 P222 = 0.635
  dimension "d842" diameter = 0.635
  dimension "d843" distance P226 P229 = 0.635
  dimension "d844" diameter = 0.635
  dimension "d845" distance P233 P236 = 0.635
  dimension "d846" diameter = 0.635
  dimension "d847" distance P240 P243 = 0.635
  dimension "d848" diameter = 0.635
  dimension "d849" distance P247 P250 = 0.635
